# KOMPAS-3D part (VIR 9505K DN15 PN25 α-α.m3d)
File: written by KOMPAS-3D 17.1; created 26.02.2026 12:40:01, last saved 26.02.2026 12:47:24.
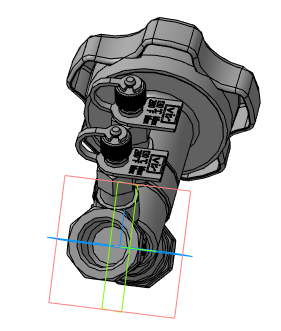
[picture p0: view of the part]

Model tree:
1. Операция без истории:4  (labels: VIR 9505K DN15 PN25 р-р)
